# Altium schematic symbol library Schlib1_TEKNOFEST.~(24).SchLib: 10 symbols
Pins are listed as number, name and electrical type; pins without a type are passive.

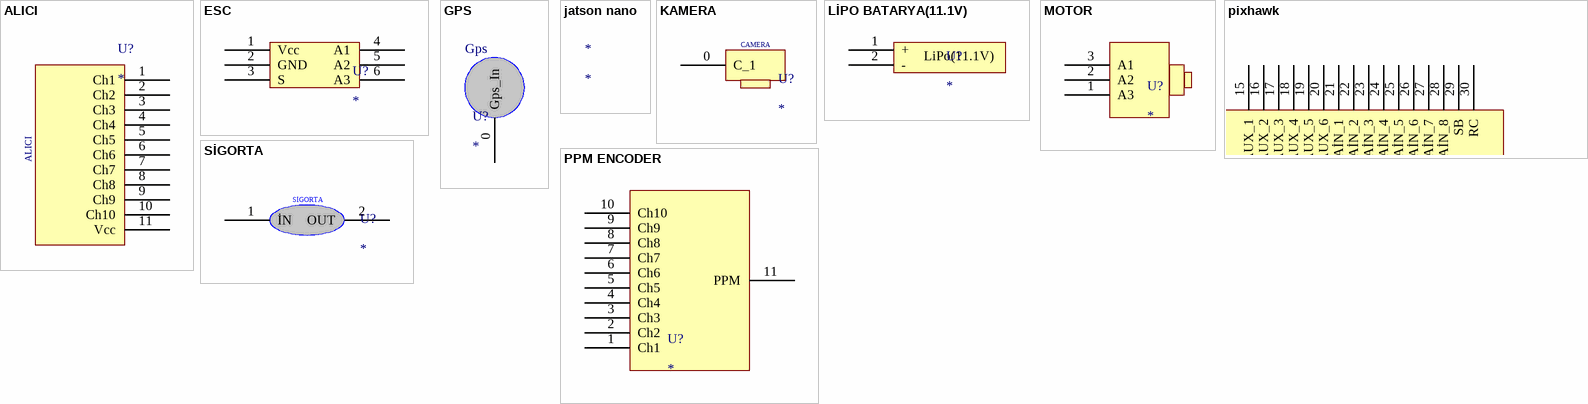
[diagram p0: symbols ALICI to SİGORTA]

## ALICI
designator U?
pins: 1 Ch1, 2 Ch2, 3 Ch3, 4 Ch4, 5 Ch5, 6 Ch6, 7 Ch7, 8 Ch8, 9 Ch9, 10 Ch10, 11 Vcc

## ESC
designator U?
pins: 1 Vcc, 2 GND, 3 S, 4 A1, 5 A2, 6 A3

## GPS
designator U?
pins: 0 Gps_In

## jatson nano
designator *

## KAMERA
designator U?
pins: 0 C_1

## LİPO BATARYA(11.1V)
designator U?
pins: 1 +, 2 -

## MOTOR
designator U?
pins: 1 A3, 2 A2, 3 A1

## pixhawk
designator U?
pins: 1 SSR, 2 SWİTCH, 3 TELEM1, 4 TELEM2, 5 USB, 6 SPI, 7 POWER, 8 BUZZER, 9 SEİAL 4/5, 10 GPS, 11 CAN, 12 I2C, 13 ADC3.3V, 14 ADC6.6V, 15 PWM AUX_1, 16 PWM AUX_2, 17 PWM AUX_3, 18 PWM AUX_4, 19 PWM AUX_5, 20 PWM AUX_6, 21 PWM MAİN_1, 22 PWM MAİN_2, 23 PWM MAİN_3, 24 PWM MAİN_4, 25 PWM MAİN_5, 26 PWM MAİN_6, 27 PWM MAİN_7, 28 PWM MAİN_8, 29 SB, 30 RC

## PPM ENCODER
designator U?
pins: 1 Ch1, 2 Ch2, 3 Ch3, 4 Ch4, 5 Ch5, 6 Ch6, 7 Ch7, 8 Ch8, 9 Ch9, 10 Ch10, 11 PPM

## SİGORTA
designator U?
pins: 1 İN, 2 OUT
